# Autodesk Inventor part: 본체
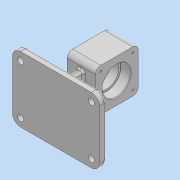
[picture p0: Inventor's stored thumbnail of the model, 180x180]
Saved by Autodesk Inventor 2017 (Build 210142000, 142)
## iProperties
Part Number: 본체
Material: 일반
Document SubType Name: Modeling
Designer: 7-1
Density: 1 g/cm^3
Appearance: 기본값
Author: 7-1
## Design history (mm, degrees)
sketch "스케치2"
  geometry: L1 (-32, 32)-(32, 32); L2 (32, 32)-(32, -32); L3 (32, -32)-(-32, -32); L4 (-32, -32)-(-32, 32); L5 (-32, 32)-(32, -32); L6 (32, 32)-(-32, -32); 1 further point
  constraints: 12 end point, 2 midpoint, 2 parallel, 1 horizontal, 1 perpendicular
  dimensions: "d0" = 64 distance of L2.end L3.end; "d1" = 64 distance of L1.end L2.end
extrude "돌출1" new body sketch "스케치2" stored distance "d2" = 42; taper "d3" = 0 deg
sketch "스케치3"
  geometry: C1 r 21 at (0, 0); 1 further point
  constraints: 1 centre point, 1 coincident
  dimensions: "d4" = 42 diameter of C1
extrude "돌출2" cut sketch "스케치3" distance "d5" = 15; taper "d6" = 0 deg
sketch "스케치4"
  geometry: C1 r 18 at (0, 0); 1 further point
  constraints: 1 centre point, 1 coincident
  dimensions: "d7" = 36 diameter of C1
extrude "돌출3" cut sketch "스케치4" stored distance "d8" = 15; taper "d9" = 0 deg
sketch "스케치5"
  geometry: C1 r 21 at (0, 0); 1 further point
  constraints: 1 centre point, 1 coincident
  dimensions: "d10" = 42 diameter of C1
extrude "돌출4" cut sketch "스케치5" distance "d11" = 15; taper "d12" = 0 deg
fillet "모깎기1" dims "d13" = 8
sketch "스케치6"
  geometry: A1 r 8 centre (-24, 24) between (-24, 32) and (-32, 24) reference; A2 r 8 centre (-24, -24) between (-32, -24) and (-24, -32) reference; A3 r 8 centre (24, -24) between (24, -32) and (32, -24) reference; A4 r 8 centre (24, 24) between (32, 24) and (24, 32) reference; 5 further points
  constraints: 4 coincident
hole "구멍1" sketch "스케치6" at (-24, -24), (24, -24), (24, 24), (-24, 24) diameter "d14" = 3.242; stored, may be unused: countersink angle "d18" = 90 deg, drill point angle "d20" = 118 deg; dims "d15" = 8, "d16" = 4, "d17" = 2, "d19" = 10
node "작업 평면1"
sketch "스케치7"
  geometry: L1 (-21, 24)-(21, 24) reference; L2 (-21, -24)-(-21, 24) reference; L3 (21, -24)-(-21, -24) reference; L4 (21, 24)-(21, -24) reference; L5 (65, -62)-(-65, -62); L6 (-65, -62)-(-65, 36); L7 (-65, 36)-(65, 36); L8 (65, 36)-(65, -62); 2 further points
  constraints: 8 end point, 2 parallel, 1 horizontal, 1 midpoint, 1 perpendicular, 1 vertical alignment
  dimensions: "d22" = 98 distance of L5.end L6.end; "d23" = 130 distance of L5.start L5.end; "d24" = 62 distance from line of point (0, 0) L5
extrude "돌출5" join sketch "스케치7" distance "d25" = 10; taper "d26" = 0 deg
sketch "스케치8"
  geometry: L1 (-17, 4)-(-4, 4); L2 (17, 4)-(17, -4); L3 (17, -4)-(4, -4); L4 (-17, -4)-(-17, 4); L5 (-4, 20)-(4, 20); L6 (4, 20)-(4, 4); L7 (4, -20)-(-4, -20); L8 (-4, -20)-(-4, -4); L9 (-4, -4)-(-17, -4); L10 (4, -4)-(-4, -4); L11 (4, -4)-(4, -20); L12 (4, 4)-(4, -4); L13 (4, 4)-(17, 4); L14 (-4, 4)-(4, 4); L15 (-4, 4)-(-4, 20); L16 (-4, -4)-(-4, 4); 5 further points
  constraints: 32 end point, 20 parallel, 6 perpendicular, 4 horizontal, 2 horizontal alignment, 2 midpoint, 2 vertical alignment
  dimensions: "d27" = 34 distance of L2.end L4.start; "d28" = 8 distance of L2.start L2.end; "d29" = 8 distance of L7.start L7.end; "d30" = 40 distance of L5.end L7.start; "d31" = 17 distance from line of L4 point (0, 0); "d32" = 20 distance from line of point (0, 0) L5; "d33" = 4 distance of point (0, 0) point (-4, 0); "d34" = 4 distance of point (0, 0) point (0, 4)
extrude "돌출6" join sketch "스케치8" stored distance "d35" = 10; taper "d36" = 0 deg
fillet "모깎기2" dims "d37" = 12
sketch "스케치9"
  geometry: A1 r 12 centre (-53, 50) between (-53, 62) and (-65, 50) reference; A2 r 12 centre (-53, -24) between (-65, -24) and (-53, -36) reference; A3 r 12 centre (53, -24) between (53, -36) and (65, -24) reference; A4 r 12 centre (53, 50) between (65, 50) and (53, 62) reference; 5 further points
  constraints: 4 coincident
hole "구멍2" sketch "스케치9" at (-53, 50), (-53, -24), (53, -24), (53, 50) diameter "d38" = 9; stored, may be unused: countersink angle "d42" = 90 deg, drill point angle "d44" = 0 deg; dims "d39" = 8, "d40" = 4, "d41" = 2, "d43" = 10
fillet "모깎기3" dims "d45" = 3
fillet "모깎기4" dims "d46" = 3
fillet "모깎기5" dims "d47" = 0.3
sketch "스케치10"
  geometry: L1 (65, 50)-(65, -24) reference; L2 (53, -36)-(-53, -36) reference; L3 (-65, -24)-(-65, 50) reference; L4 (-53, 62)-(53, 62) reference; C1 r 4.5 at (53, -24) reference; C2 r 4.5 at (-53, 50) reference; C3 r 4.5 at (-53, -24) reference; C4 r 4.5 at (53, 50) reference; A1 r 12 centre (53, 50) between (65, 50) and (53, 62) reference; A2 r 12 centre (53, -24) between (53, -36) and (65, -24) reference; A3 r 12 centre (-53, -24) between (-65, -24) and (-53, -36) reference; A4 r 12 centre (-53, 50) between (-53, 62) and (-65, 50) reference; 2 further points
  constraints: 1 vertical alignment, 1 other
  dimensions: "d48" = 10 distance from line of L4 point (0, 52)
feature "엠보싱1" sketch "스케치10" dims "d0" = 64, "d1" = 64, "d11" = 15, "d12" = 0, "d49" = 0.5, "d50" = 0
chamfer "모따기1" distance "d51" = 1; stored, may be unused: second distance "d52" = 2, angle "d53" = 45 deg
chamfer "모따기2" distance "d54" = 1; stored, may be unused: second distance "d55" = 2, angle "d56" = 45 deg
node "솔리드1"
mirror "미러1"
node "투영된 루프1"
node "투영된 루프2"
